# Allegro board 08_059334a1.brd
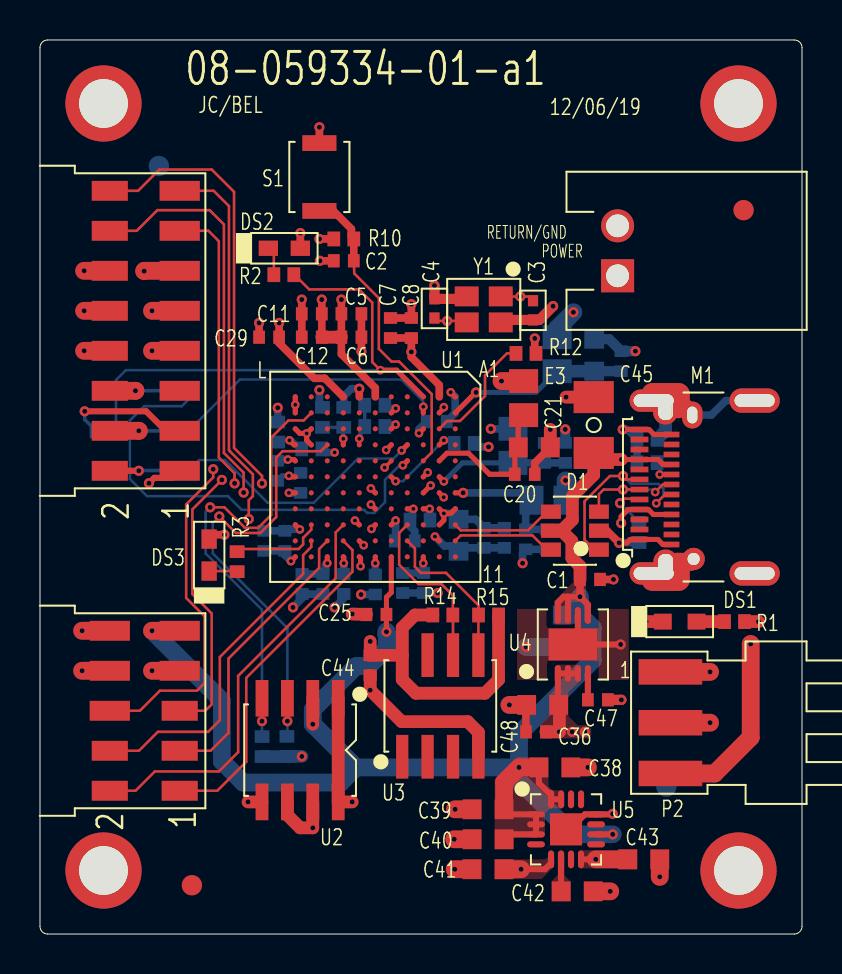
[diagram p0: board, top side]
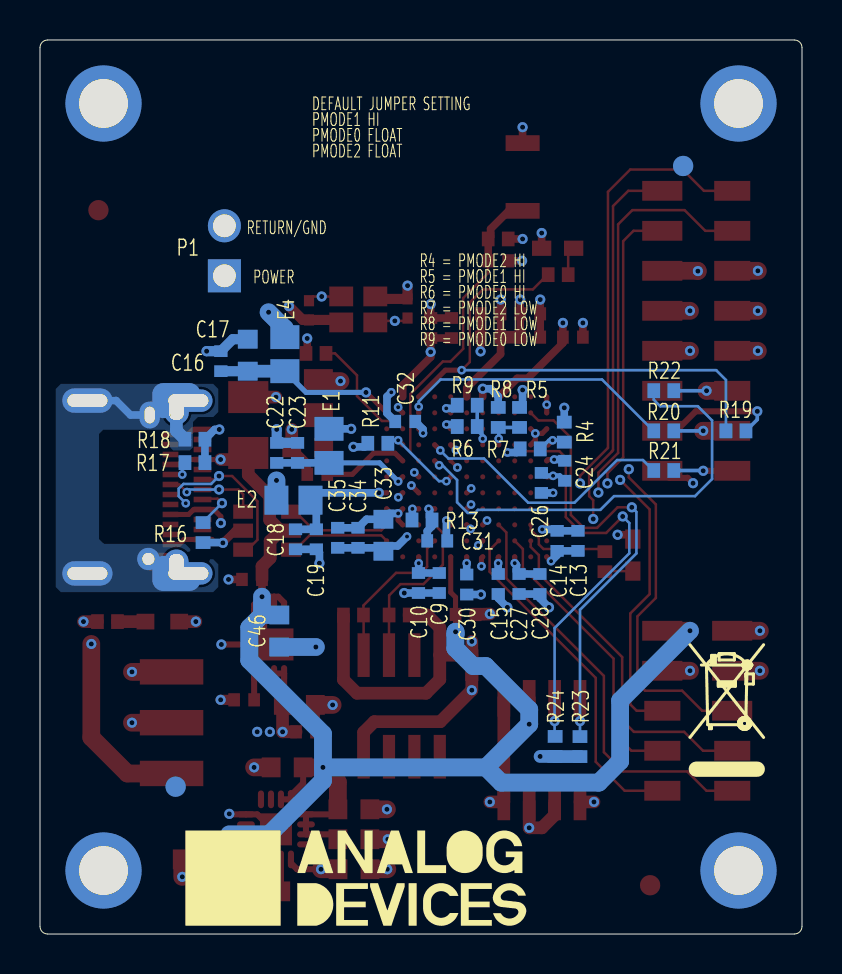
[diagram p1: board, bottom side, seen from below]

Outline 38.1 x 44.7 mm; copper layers: TOP, L2_GND, L3_SIG, L4_PWR, L5_GND, BOTTOM. Coordinates in mm from the lower left corner of the outline.
Outline path: 0,44.32 0,0.38 arc(0.11,0.11) 0.38,0 37.72,0 arc(37.99,0.11) 38.1,0.38 38.1,44.32 arc(37.99,44.59) 37.72,44.7 0.38,44.7 arc(0.11,44.59) 0,44.32

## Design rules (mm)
constraint set DEFAULT: min track width 0.127

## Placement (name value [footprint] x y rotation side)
C1  1uF  [C0402]  27.5 17.73 0 top
C2  0.1uF  [C0402]  15.19 33.66 180 top
C3  13PF  [C0402H22]  24.65 31.19 270 top
C4  13PF  [C0402H22]  19.72 31.28 90 top
C5  0.1uF  [C0402]  15.57 31.01 0 top
C6  0.1uF  [C0402]  15.57 29.84 0 top
C7  0.1uF  [C0402]  17.53 30.3 90 top
C8  0.01UF  [C0402]  18.57 30.3 90 top
C9  0.1uF  [C0402]  18.14 17.55 270 bottom
C10  0.01UF  [C0402]  19.18 17.55 270 bottom
C11  0.1uF  [C0402]  13.59 31.01 180 top
C12  0.1uF  [C0402]  13.59 29.84 180 top
C13  0.1uF  [C0402]  11.2 19.66 270 bottom
C14  0.1uF  [C0402]  12.24 19.66 270 bottom
C15  0.01UF  [C0402]  15.19 17.5 270 bottom
C16  0.1uF  [C0402]  29.06 28.64 90 bottom
C17  22uF  [C0603]  27.71 28.94 90 bottom
C18  2.2uF  [C0402]  25.32 19.74 270 bottom
C19  0.1uF  [C0402]  24.28 19.74 270 bottom
C20  0.1uF  [C0402]  24.24 22.99 0 top
C21  22uF  [C0603]  24.71 24.33 0 top
C22  0.01UF  [C0402]  26.26 24.06 90 bottom
C23  0.1uF  [C0402]  25.22 24.06 90 bottom
C24  0.1uF  [C0402]  11.86 23.16 270 bottom
C25  0.1uF  [C0402]  16.82 15.98 180 top
C26  0.1uF  [C0402]  13.03 22.56 90 bottom
C27  0.01UF  [C0402]  14.15 17.5 270 bottom
C28  0.1uF  [C0402]  13.11 17.5 270 bottom
C29  0.1uF  [C0402]  11.46 29.84 180 top
C30  0.1uF  [C0402]  16.76 17.48 270 bottom
C31  0.01UF  [C0402]  18.24 19.66 0 bottom
C32  0.01UF  [C0402]  19.84 25.63 0 bottom
C33  22uF  [C0603]  20.93 19.94 90 bottom
C34  0.1uF  [C0402]  22.2 19.81 90 bottom
C35  0.01UF  [C0402]  23.22 19.81 90 bottom
C36  1uF  [C0402]  24.8 10.11 180 top
C38  4.7uF  [C0603]  25.74 8.33 0 top
C39  4.7uF  [C0603]  22.41 6.24 180 top
C40  4.7uF  [C0603]  22.41 4.74 180 top
C41  4.7uF  [C0603]  22.4 3.24 180 top
C42  4.7uF  [C0603]  26.86 2.13 0 top
C43  4.7uF  [C0603]  30.19 3.73 0 top
C44  0.1uF  [C0402]  16.51 13.44 270 top
C45  10UF  [C1206H71]  27.69 25.45 90 top
C46  10uF  [C0603]  26.14 15.15 270 bottom
C47  1UF  [C0402]  27.89 11.71 0 top
C48  10uF  [C0603]  25.13 11.46 180 top
D1  82400102  [SOT23_6-2]  26.75 20.17 90 top
DS1  LTST-C191KGKT  [LED0603_A]  31.98 15.62 0 top
DS2  LTST-C191KSKT  [LED0603]  12.22 34.29 0 top
DS3  LTST-C191KSKT  [LED0603]  8.46 18.95 90 top
E1  600OHM AT 100MEGHZ  [L0805]  23.65 24.41 270 bottom
E2  600OHM AT 100MEGHZ  [L0805]  25.43 21.69 180 bottom
E3  600OHM AT 100MEGHZ  [L0805]  24.18 26.8 90 top
E4  600OHM AT 100MEGHZ  [L0805]  25.86 28.99 90 bottom
M1  DX07S024JJ3  [MDX07S024JJ3]  37.53 22.35 90 top
NOREF  -  []  13.9 20.16 0 top
NOREF#2  -  [unnamed#2]  30.68 18.03 270 top
NOREF#3  -  [unnamed#2]  34.92 41.53 0 top
NOREF#4  -  [unnamed#2]  30.68 26.67 270 top
NOREF#5  -  []  3.56 0 90 top
NOREF#6  -  []  0 1.44 0 top
NOREF#7  -  []  -234.21 -121.03 0 top
NOREF#8  -  []  -229.13 283.51 0 top
NOREF#9  -  [unnamed#2]  35.18 36.2 0 top
NOREF#10  -  [unnamed#2]  34.92 3.18 0 top
NOREF#11  -  [unnamed#2]  31.27 26.35 0 top
NOREF#12  -  [unnamed#2]  3.18 3.18 0 top
NOREF#13  -  []  3.18 41.53 0 top
NOREF#14  -  []  34.92 3.18 90 top
NOREF#15  -  []  37.99 44.59 0 top
NOREF#16  -  [unnamed#2]  7.59 2.44 0 top
NOREF#17  -  []  38.02 0.14 0 top
NOREF#18  -  []  0.08 44.55 0 top
NOREF#19  -  [unnamed#2]  3.18 41.53 0 top
NOREF#20  -  []  9.89 4.16 0 top
NOREF#21  -  [unnamed#2]  31.28 18.35 0 top
NOREF#22  -  []  37.53 28.36 0 top
NOREF#23  -  []  0.12 0.1 0 top
NOREF#24  -  []  3.96 7.92 180 bottom
NOREF#25  -  [unnamed#2]  5.94 38.4 180 bottom
NOREF#26  -  [unnamed#2]  31.32 7.37 180 bottom
NOREF#27  -  []  22.28 2.79 180 bottom
P1  S2B-XH-A(LF)(SN)  [CNTHMHDRRA1X2L291W452H240]  28.88 32.91 90 top
P2  TSM-103-01-L-SH  [CNSMMHDRRA1X3L300W100H125]  36.8 10.57 270 top
P3  10112690-G03-08ULF  [CNSMMHDRRA2X8L630W59H169]  0.74 30.16 90 top
P4  10112690-G03-05ULF  [CNSMMHDRRA2X5L394W59H169]  0.74 11.16 90 top
R1  330  [R0402]  34.73 15.62 180 top
R2  330  [R0402]  12.19 32.97 0 top
R3  330  [R0402]  9.86 18.62 90 top
R4  0  [R0402]  11.89 25.1 270 bottom
R5  0  [R0402]  14.12 25.83 270 bottom
R6  0  [R0402]  16.74 25.37 180 bottom
R7  0  [R0402]  13.59 24.26 0 bottom
R8  0  [R0402]  15.19 25.83 90 bottom
R9  0  [R0402]  16.74 26.44 0 bottom
R10  100K  [R0402]  15.19 34.75 0 top
R11  10K  [R0402]  21.21 24.54 180 bottom
R12  200  [R0402]  24.3 29.03 0 top
R13  6.04K  [R0402]  19 20.7 180 bottom
R14  2K  [R0402]  20.14 15.95 0 top
R15  2K  [R0402]  22.43 15.95 180 top
R16  5.1K  [R0402]  29.95 20.07 270 bottom
R17  5.1K  [R0402]  30.35 23.57 180 bottom
R18  0  [R0402]  30.35 24.74 180 bottom
R19  22  [R0402]  3.3 25.16 180 bottom
R20  22  [R0402]  6.91 25.16 0 bottom
R21  22  [R0402]  6.91 23.18 0 bottom
R22  22  [R0402]  6.91 27.17 0 bottom
R23  10K  [R0402]  11.1 9.37 270 bottom
R24  10K  [R0402]  12.34 9.38 270 bottom
S1  B3U-1000P  [SWSML118W98H69]  13.97 37.85 270 top
U1  CYUSB3014-BZXC  [BGA121_A]  16.76 22.86 180 top
U2  LTC1470CS8#PBF  [SO8NB-5]  13 9.19 180 top
U3  M24M02-DRMN6TP  [SO8]  20.02 11.4 0 top
U4  ADM7172ACPZ-3.3  [DFN8_3X3_PAD2_44X1_6_A]  26.64 14.48 0 top
U5  ADP322ACPZ-165  [QFN16_3X3_PAD1_6X1_6]  26.3 5.23 270 top
Y1  19.200MEGHZ  [YSML98W79H26]  22.19 31.23 180 top

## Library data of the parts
C1 C36 = CAP: User Part Number: UPN; Tolerance: 20; alternate symbols: (); part number: CAP_SM-1UF,16V,20,E020695,C0402; tolerance: 20
C2 C5-C7 C9 C11-C14 C16 C19 C20 C23-C26 C28-C30 C34 C44 = CAP: User Part Number: UPN; Tolerance: 10; alternate symbols: (); part number: CAP_SM-0.1UF,10V,10,E016510,C0402; tolerance: 10
C3 C4 = CAP: Tolerance: 5; User Part Number: UPN; alternate symbols: (); part number: CAP_SM-13PF,50V,5,E033176,C0402H22; tolerance: 5
C8 C10 C15 C22 C27 C31 C32 C35 = CAP: User Part Number: UPN; Tolerance: 10; alternate symbols: (); part number: CAP_SM-0.01UF,25V,10,E007203,C0402; tolerance: 10
C17 C21 C33 = CAP: User Part Number: UPN; Tolerance: 20; alternate symbols: (); part number: CAP_SM-22UF,4V,20,E017158,C0603; tolerance: 20
C18 = CAP: User Part Number: UPN; Tolerance: 10; alternate symbols: (); part number: CAP_SM-2.2UF,6.3V,10,E021628,C0402; tolerance: 10
C38-C43 = CAP: User Part Number: UPN; Tolerance: 10; alternate symbols: (); part number: CAP_SM-4.7UF,16V,10,E020112,C0603; tolerance: 10
C45 = CAP: Tolerance: 10; User Part Number: UPN; alternate symbols: (); part number: CAP_SM-10UF,50V,10,E026881,C1206H71; tolerance: 10
C46 C48 = CAP: User Part Number: UPN; Tolerance: 20; alternate symbols: (); part number: CAP_SM-10UF,16V,20,E020896,C0603; tolerance: 20
C47 = CAP: User Part Number: UPN; Tolerance: 20; alternate symbols: (); part number: CAP_SM-1UF,16V,20,E030046,C0402; tolerance: 20
D1 = DIOTVS6P: User Part Number: UPN; Tolerance: N/A; alternate symbols: (); part number: DIOTVS6P_SM-82400102,5V,N/A,E023105,SOT23_6-2; tolerance: N/A
DS1 = DIOLED: User Part Number: UPN; Tolerance: N/A; alternate symbols: (); part number: DIOLED_SM-LTST-C191KGKT,2V,N/A,E033001,LED0603_A; tolerance: N/A
DS2 DS3 = DIOLED: Tolerance: N/A; User Part Number: UPN; alternate symbols: (); part number: DIOLED_SM-LTST-C191KSKT,2V,N/A,E025936,LED0603; tolerance: N/A
E1-E4 = FERRITE: User Part Number: UPN; Tolerance: 25; alternate symbols: (); part number: FERRITE_SM-600OHM AT 100MEGHZ,25,E022193,L0805; tolerance: 25
M1 = MODUSB24P_6PSHLD: User Part Number: UPN; Tolerance: N/A; alternate symbols: (); part number: MODUSB24P_6PSHLD_SM-DX07S024JJ3,E025013,MDX07S024JJ3; tolerance: N/A
P1 = CN2P: User Part Number: UPN; Tolerance: N/A; alternate symbols: (); part number: CN2P_TH-S2B-XH-A(LF)(SN),E032336,CNTHMHDRRA1X2L291W452H240; tolerance: N/A
P2 = CN3P: User Part Number: UPN; Tolerance: N/A; alternate symbols: (); part number: CN3P_SM-TSM-103-01-L-SH,E038809,CNSMMHDRRA1X3L300W100H125; tolerance: N/A
P3 = CN16P_ODD_EVEN: User Part Number: UPN; Tolerance: N/A; alternate symbols: (CNSMMHDRRA2X8L630W59H169X); part number: CN16P_ODD_EVEN_SM-10112690-G03-08ULF,E038806,CNSMMHDRRA2X8L630W59H169; tolerance: N/A
P4 = CN10P_ODD_EVEN: User Part Number: UPN; Tolerance: N/A; alternate symbols: (CNSMMHDRRA2X5L394W59H169X); part number: CN10P_ODD_EVEN_SM-10112690-G03-05ULF,E038807,CNSMMHDRRA2X5L394W59H169; tolerance: N/A
R1-R3 = RES: User Part Number: UPN; Tolerance: 5; alternate symbols: (R0402L); part number: RES_SM-330,E003462,1/16W,5,R0402; tolerance: 5
R4-R9 R18 = RES: User Part Number: UPN; Tolerance: N/A; alternate symbols: (); part number: RES_SM-0,E030156,1/16W,N/A,R0402; tolerance: N/A
R10 = RES: User Part Number: UPN; Tolerance: 1; alternate symbols: (R0402L,R0402L_ALT); part number: RES_SM-100K,E003796,1/16W,1,R0402; tolerance: 1
R11 R23 R24 = RES: User Part Number: UPN; Tolerance: 1; alternate symbols: (R0402L,R0402L_ALT); part number: RES_SM-10K,E003751,1/10W,1,R0402; tolerance: 1
R12 = RES: User Part Number: UPN; Tolerance: 1; alternate symbols: (R0402L); part number: RES_SM-200,E003753,1/10W,1,R0402; tolerance: 1
R13 = RES: User Part Number: UPN; Tolerance: 1; alternate symbols: (R0402L); part number: RES_SM-6.04K,E004030,1/16W,1,R0402; tolerance: 1
R14 R15 = RES: User Part Number: UPN; Tolerance: 1; alternate symbols: (R0402L,R0402L_ALT); part number: RES_SM-2K,E003752,1/10W,1,R0402; tolerance: 1
R16 R17 = RES: User Part Number: UPN; Tolerance: 1; alternate symbols: (R0402L); part number: RES_SM-5.1K,E019615,1/16W,1,R0402; tolerance: 1
R19-R22 = RES: User Part Number: UPN; Tolerance: 5; alternate symbols: (); part number: RES_SM-22,E033672,1/10W,5,R0402; tolerance: 5
S1 = SWSPST2PIN_V2: Tolerance: N/A; User Part Number: UPN; alternate symbols: (); part number: SWSPST2PIN_V2_SM-B3U-1000P,E016303,SWSML118W98H69; tolerance: N/A
U1 = ICCYUSB301X: User Part Number: UPN; Tolerance: N/A; alternate symbols: (); part number: ICCYUSB301X_SM-CYUSB3014-BZXC,E022930,BGA121_A; tolerance: N/A
U2 = ADLTC1470: Tolerance: N/A; User Part Number: UPN; alternate symbols: (); part number: ADLTC1470_SM-LTC1470CS8#PBF,E039502,SO8NB-5; tolerance: N/A
U3 = ICM24M02: Tolerance: N/A; User Part Number: UPN; alternate symbols: (); part number: ICM24M02_SM-M24M02-DRMN6TP,E023121,SO8; tolerance: N/A
U4 = ADM7172: Tolerance: N/A; User Part Number: UPN; alternate symbols: (); part number: ADM7172_SM-ADM7172ACPZ-3.3,E022887,DFN8_3X3_PAD2_44X1_6_A; tolerance: N/A
U5 = ADP322: User Part Number: UPN; Tolerance: N/A; alternate symbols: (); part number: ADP322_SM-ADP322ACPZ-165,E038808,QFN16_3X3_PAD1_6X1_6; tolerance: N/A
Y1 = XTAL4PIN_V3: Tolerance: N/A; User Part Number: UPN; alternate symbols: (); part number: XTAL4PIN_V3_SM-19.200MEGHZ,E023118,YSML98W79H26; tolerance: N/A

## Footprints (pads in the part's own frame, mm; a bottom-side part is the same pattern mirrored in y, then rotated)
BGA121_A
  round 0.254 smd: A1(-4,-4) A2(-4,-3.2) A3(-4,-2.4) A4(-4,-1.6) A5(-4,-0.8) A6(-4,0) A7(-4,0.8) A8(-4,1.6) A9(-4,2.4) A10(-4,3.2) A11(-4,4) B1(-3.2,-4) B2(-3.2,-3.2) B3(-3.2,-2.4) B4(-3.2,-1.6) B5(-3.2,-0.8) B6(-3.2,0) B7(-3.2,0.8) B8(-3.2,1.6) B9(-3.2,2.4) B10(-3.2,3.2) B11(-3.2,4) C1(-2.4,-4) C2(-2.4,-3.2) C3(-2.4,-2.4) C4(-2.4,-1.6) C5(-2.4,-0.8) C6(-2.4,0) C7(-2.4,0.8) C8(-2.4,1.6) C9(-2.4,2.4) C10(-2.4,3.2) C11(-2.4,4) D1(-1.6,-4) D2(-1.6,-3.2) D3(-1.6,-2.4) D4(-1.6,-1.6) D5(-1.6,-0.8) D6(-1.6,0) D7(-1.6,0.8) D8(-1.6,1.6) D9(-1.6,2.4) D10(-1.6,3.2) D11(-1.6,4) E1(-0.8,-4) E2(-0.8,-3.2) E3(-0.8,-2.4) E4(-0.8,-1.6) E5(-0.8,-0.8) E6(-0.8,0) E7(-0.8,0.8) E8(-0.8,1.6) E9(-0.8,2.4) E10(-0.8,3.2) E11(-0.8,4) F1(0,-4) F2(0,-3.2) F3(0,-2.4) F4(0,-1.6) F5(0,-0.8) F6(0,0) F7(0,0.8) F8(0,1.6) F9(0,2.4) F10(0,3.2) F11(0,4) G1(0.8,-4) G2(0.8,-3.2) G3(0.8,-2.4) G4(0.8,-1.6) G5(0.8,-0.8) G6(0.8,0) G7(0.8,0.8) G8(0.8,1.6) G9(0.8,2.4) G10(0.8,3.2) G11(0.8,4) H1(1.6,-4) H2(1.6,-3.2) H3(1.6,-2.4) H4(1.6,-1.6) H5(1.6,-0.8) H6(1.6,0) H7(1.6,0.8) H8(1.6,1.6) H9(1.6,2.4) H10(1.6,3.2) H11(1.6,4) J1(2.4,-4) J2(2.4,-3.2) J3(2.4,-2.4) J4(2.4,-1.6) J5(2.4,-0.8) J6(2.4,0) J7(2.4,0.8) J8(2.4,1.6) J9(2.4,2.4) J10(2.4,3.2) J11(2.4,4) K1(3.2,-4) K2(3.2,-3.2) K3(3.2,-2.4) K4(3.2,-1.6) K5(3.2,-0.8) K6(3.2,0) K7(3.2,0.8) K8(3.2,1.6) K9(3.2,2.4) K10(3.2,3.2) K11(3.2,4) L1(4,-4) L2(4,-3.2) L3(4,-2.4) L4(4,-1.6) L5(4,-0.8) L6(4,0) L7(4,0.8) L8(4,1.6) L9(4,2.4) L10(4,3.2) L11(4,4)
C0402
  rect 0.584x0.66 smd: 1(-0.5,0) 2(0.5,0)
C0402H22
  rect 0.559x0.508 smd: 1(-0.48,0) 2(0.48,0)
C0603
  rect 0.94x0.991 smd: 1(-0.8,0) 2(0.8,0)
C1206H71
  rect 1.6x2.007 smd: 1(-1.397,0) 2(1.397,0)
CNSMMHDRRA1X3L300W100H125
  rect 1.27x3.175 smd: 1(-2.54,-5.283) 2(0,-5.283) 3(2.54,-5.283)
CNSMMHDRRA2X5L394W59H169
  rect 0.991x1.803 smd: 1(-4,-6.248) 2(-4,-2.753) 3(-2,-6.248) 4(-2,-2.753) 5(0,-6.248)
  rect 0.991x2.007 smd: 6(0,-2.753) 7(2,-6.248) 8(2,-2.753) 9(4,-6.248) 10(4,-2.753)
CNSMMHDRRA2X8L630W59H169
  rect 0.991x2.007 smd: 1(-7,-6.248) 3(-5,-6.248) 5(-3,-6.248) 7(-1,-6.248) 9(1,-6.248) 11(3,-6.248) 13(5,-6.248) 15(7,-6.248)
  rect 0.991x1.803 smd: 2(-7,-2.753) 4(-5,-2.753) 6(-3,-2.753) 8(-1,-2.753) 10(1,-2.753) 12(3,-2.753) 14(5,-2.753) 16(7,-2.753)
CNTHMHDRRA1X2L291W452H240
  rect 1.651x1.651 hole 1.143: 1(0,0)
  round 1.651 hole 1.143: 2(2.499,0)
DFN8_3X3_PAD2_44X1_6_A
  oval 0.305x0.838 smd: 1(-0.749,-1.45) 2(-0.249,-1.45) 3(0.249,-1.45) 4(0.749,-1.45) 5(0.749,1.45) 6(0.249,1.45) 7(-0.249,1.45) 8(-0.749,1.45)
  rect 2.438x1.6 smd: PAD(0,0)
L0805
  rect 1.194x1.448 smd: 1(-0.851,0) 2(0.851,0)
LED0603
  rect 0.965x0.762 smd: A(0.8,0) C(-0.8,0)
LED0603_A
  rect 0.889x0.787 smd: A(0.843,0) C(-0.843,0)
MDX07S024JJ3
  oval 1.219x2.515 hole 0.635x2.007 unplated: (-4.32,1.801) (4.32,1.801)
  oval 1.346x1.016 hole 0.838x0.508 unplated: (3.599,4.915)
  rect 0.279x0.889 smd: A1(-2.624,7.556) A2(-2.126,7.556) A3(-1.626,7.556) A4(-1.125,7.556) A5(-0.625,7.556) A6(-0.125,7.556) A7(0.376,7.556) A8(0.874,7.556) A9(1.374,7.556) A10(1.874,7.556) A11(2.375,7.556) A12(2.875,7.556)
  rect 0.279x0.787 smd: B1(2.624,5.956) B2(2.126,5.956) B3(1.626,5.956) B4(1.125,5.956) B5(0.625,5.956) B6(0.125,5.956) B7(-0.376,5.956) B8(-0.874,5.956) B9(-1.374,5.956) B10(-1.874,5.956) B11(-2.375,5.956) B12(-2.875,5.956)
  custom 0.438x0.438 hole 0.002: SH4(4.32,6.251) SH5(-4.32,6.251)
  round 1.118 hole 0.61: SH6(-3.599,4.849)
QFN16_3X3_PAD1_6X1_6
  oval 0.305x0.889 smd: 1(-0.749,-1.501) 2(-0.249,-1.501) 3(0.249,-1.501) 4(0.749,-1.501) 9(0.749,1.501) 10(0.249,1.501) 11(-0.249,1.501) 12(-0.749,1.501)
  oval 0.889x0.305 smd: 5(1.501,-0.749) 6(1.501,-0.249) 7(1.501,0.249) 8(1.501,0.749) 13(-1.501,0.749) 14(-1.501,0.249) 15(-1.501,-0.249) 16(-1.501,-0.749)
  rect 1.6x1.6 smd: PAD(0,0)
R0402
  rect 0.635x0.737 smd: 1(-0.5,0) 2(0.5,0)
SO8
  rect 0.61x2.184 smd: 1(-1.905,-2.54) 2(-0.635,-2.54) 3(0.635,-2.54) 4(1.905,-2.54) 5(1.905,2.54) 6(0.635,2.54) 7(-0.635,2.54) 8(-1.905,2.54)
SO8NB-5
  rect 0.635x1.829 smd: 1(-1.905,-2.591) 2(-0.635,-2.591) 3(0.635,-2.591) 4(1.905,-2.591) 5(1.905,2.591) 6(0.635,2.591) 7(-0.635,2.591) 8(-1.905,2.591)
SOT23_6-2
  rect 0.711x0.991 smd: 1(-0.95,-1.199) 2(0,-1.199) 3(0.95,-1.199) 4(0.95,1.199) 5(0,1.199) 6(-0.95,1.199)
SWSML118W98H69
  rect 0.787x1.702 smd: 1(-1.694,0) 2(1.694,0)
unnamed#2
  oval 1.118x2.413 hole 0.635x2.007 unplated: (0,0)
YSML98W79H26
  rect 1.194x0.991 smd: 1(-0.851,-0.65) 2(0.851,-0.65) 3(0.851,0.65) 4(-0.851,0.65)

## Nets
AVDD: C18.1 C19.1 E2.2(N2) U1.A7
DGND: C1.2(N2) C2.2(N2) C3.2(N2) C4.2(N2) C5.2(N2) C6.2(N2) C7.2(N2) C8.2(N2) C9.2(N2) C10.2(N2) C11.2(N2) C12.2(N2) C13.2(N2) C14.2(N2) C15.2(N2) C16.2(N2) C17.2(N2) C18.2(N2) C19.2(N2) C20.2(N2) C21.2(N2) C22.2(N2) C23.2(N2) C24.2(N2) C25.2(N2) C26.2(N2) C27.2(N2) C28.2(N2) C29.2(N2) C30.2(N2) C31.2(N2) C32.2(N2) C33.2(N2) C34.2(N2) C35.2(N2) C36.2(N2) C38.2(N2) C39.2(N2) C40.2(N2) C41.2(N2) C42.2(N2) C43.2(N2) C44.2(N2) C45.2(N2) C46.2(N2) C47.2(N2) C48.2(N2) D1.2 DS1.C M1.A1 M1.A12 M1.B1 M1.B12 P1.2(N2) P3.7 P3.8 P3.9 P4.7 P4.8 R7.2(N2) R8.2(N2) R9.2(N2) R11.1 R12.2(N2) R13.2(N2) R16.2(N2) R17.2(N2) R18.2(N2) S1.1 U1.A1 U1.A8 U1.B7 U1.B8 U1.B9 U1.D8 U1.E2 U1.G1 U1.G11 U1.K3 U1.K4 U1.L1 U1.L2 U1.L3 U1.L6 U1.L11 U2.5 U3.4 U4.6 U4.PAD U5.12 U5.PAD Y1.2 Y1.4
DUT_3P3V: C36.1 C48.1 U2.6 U2.7 U4.1 U4.2(VOUT2) U4.3
DUT_EXT: P1.1 P2.3(N3)
DUT_REG_PWR: P2.1 U2.1 U2.8(OUT_2)
DUT_SUPPLY: P2.2 P3.10 P3.11 P3.12
FX3_1P2V: C24.1 C26.1 C27.1 C28.1 C29.1 C30.1 C31.1 C32.1 C33.1 C34.1 C35.1 C43.1 E2.1 E3.2(N2) E4.2(N2) U1.B10 U1.C3 U1.E9 U1.F11 U1.H1 U1.J11 U1.L5 U1.L7 U5.8(VOUT3)
FX3_1P8V: C42.1 U5.6
FX3_3P3V: C5.1 C6.1 C7.1 C8.1 C9.1 C10.1 C11.1 C12.1 C13.1 C14.1 C15.1 C41.1 C44.1 DS2.A(P) DS3.A(P) E1.1 P4.10(N5) R1.1 R4.1 R5.1 R6.1 R10.1 R14.1 R15.1 R23.2(N2) R24.2(N2) U1.B1 U1.C11 U1.E3 U1.F1 U1.H11 U1.L9 U3.8 U5.5
FX3_CTL0: U1.K8
FX3_CTL1: U1.K7
FX3_CTL2: U1.J7
FX3_CTL3: U1.H7
FX3_CTL4: U1.G7
FX3_CTL5: U1.G6
FX3_CTL6: U1.K6
FX3_CTL7: U1.H8
FX3_CTL8: U1.G5
FX3_CTL9: U1.H6
FX3_CTL10: U1.K5
FX3_CTL11: U1.J5
FX3_CTL12: U1.H5
FX3_DQ0: P3.1 U1.F9
FX3_DQ1: P3.16(N8) U1.F7
FX3_DQ2: P3.15 U1.G10
FX3_DQ3: P3.14 U1.G9
FX3_DQ4: P3.13 U1.F8
FX3_DQ5: P4.1 U1.H10
FX3_DQ6: P4.2 U1.H9
FX3_DQ7: P4.3 U1.J10
FX3_DQ8: U1.J9
FX3_DQ9: U1.K11
FX3_DQ10: U1.F10
FX3_DQ11: U1.L10
FX3_DQ12: P4.4 U1.K10
FX3_DQ13: R3.2(N2) U1.K9
FX3_DQ14: U1.J8
FX3_DQ15: U1.G8
FX3_DQ16: R23.1 U1.K2 U2.4
FX3_DQ17: R24.1 U1.J4 U2.3
FX3_DQ18: U1.K1
FX3_DQ19: U1.J2
FX3_DQ20: U1.J3
FX3_DQ21: U1.J1
FX3_DQ22: U1.H2
FX3_DQ23: U1.H3
FX3_DQ24: U1.F4
FX3_DQ25: U1.G2
FX3_DQ26: U1.G3
FX3_DQ27: U1.F3
FX3_DQ28: U1.F5
FX3_DQ29: U1.E1
FX3_DQ30: P4.5 U1.E5
FX3_DQ31: P4.6 U1.E4
FX3_GPIO_52: U1.D3
FX3_GPIO_57: U1.C4
FX3_PCLK: U1.J6
FX3_PMODE_0: R6.2(N2) R9.1 U1.G4
FX3_PMODE_1: R5.2(N2) R8.1 U1.H4
FX3_PMODE_2: R4.2(N2) R7.1 U1.L4
FX3_SCL: R14.2(N2) U1.D9 U3.6
FX3_SDA: R15.2(N2) U1.D10 U3.5
FX3_STATUS: U1.F2
FX3_VBUS: C1.1 C25.1 C38.1 C39.1 C40.1 C45.1 C46.1 D1.5(VDD) M1.A4 M1.A9 M1.B4(VBUS_4) M1.B9 P4.9 U1.E11 U2.2 U4.5 U4.7 U4.8 U5.1 U5.2 U5.3 U5.10 U5.15 U5.16
SPI_CSB: R2.2(N2) R19.1 U1.C1
SPI_CSB2: U1.D1
SPI_CSB3: U1.D2
SPI_MISO: R20.2(N2) U1.C2
SPI_MOSI: R22.2(N2) U1.D5
SPI_SCLK: R21.2(N2) U1.D4
SS_DM: D1.6 U1.A10
SS_DP: D1.4 U1.A9
SSDM: D1.1 M1.A7 M1.B7
SSDP: D1.3 M1.A6 M1.B6
U3RX_VDDQ: C16.1 C17.1 E4.1 U1.A2
U3TX_VDDQ: C20.1 C21.1 E3.1 U1.B5
UNNAMED_4_ADM7172_I197_SS: C47.1 U4.4
UNNAMED_4_CAP_I116_N1: C2.1 R10.2(N2) S1.2(B) U1.C5
UNNAMED_4_CAP_I140_N1: C22.1 C23.1 E1.2(N2) U1.B6
UNNAMED_4_CN16PODDEVEN_I209_N2: P3.3 R19.2(N2)
UNNAMED_4_CN16PODDEVEN_I210_N1: P3.2 R21.1
UNNAMED_4_CN16PODDEVEN_I210_N2: P3.4 R20.1
UNNAMED_4_CN16PODDEVEN_I210_N3: P3.6 R22.1
UNNAMED_4_DIOLED_I220_N: DS3.C R3.1
UNNAMED_4_DIOLED_I221_N: DS2.C R2.1
UNNAMED_4_DIOLED_I222_P: DS1.A(P) R1.2(N2)
UNNAMED_4_ICCYUSB301X_I101_FSLC: R11.2(N2) U1.B2 U1.B4 U1.E6
UNNAMED_4_ICCYUSB301X_I101_RU_1: R12.1 U1.B3
UNNAMED_4_ICCYUSB301X_I101_RUSB: R13.1 U1.C8
UNNAMED_4_MODUSB24P6PSHLD_I16_1: M1.B5 R17.1
UNNAMED_4_MODUSB24P6PSHLD_I16_2: M1.SH4 M1.SH5 M1.SH6 R18.1
UNNAMED_4_MODUSB24P6PSHLD_I165_: M1.A5 R16.1
XTALIN: C4.1 U1.C6 Y1.3(N2)
XTALOUT: C3.1 U1.C7(XTALOUT) Y1.1

Pads without a net: M1 A2 A3 A8 A10 A11 B2 B3 B8 B10 B11; P3 5; U1 A3 A4 A5 A6 A11 B11 C9 C10 D6 D7 D11 E7 E8 E10 F6 L8; U3 1 2 3 7; U5 4 7 9 11 13 14

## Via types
v1: diameter 0.508, hole 0.254, TOP to BOTTOM, 103 vias
v2: diameter 0.432, hole 0.203, TOP to BOTTOM, 46 vias

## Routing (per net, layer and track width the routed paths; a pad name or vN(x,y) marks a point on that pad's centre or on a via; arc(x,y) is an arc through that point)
AVDD: length 6.6
  TOP w0.254: U1.A7 v1(21.16,22.06)
  BOTTOM w0.381: v1(21.16,22.06) 24.21,22.06 E2.2 24.28,21.4 C19.1 C18.1
DGND: length 101.3
  TOP w0.254: v2(20.19,21.03) 20.19,20.69 U1.B9 ; v2(20.19,21.03) 20.54,21.03 U1.A8 ; v2(20.19,21.03) U1.B8 ; M1.B1 30.7,24.98 30.45,25.23 M1.A12 v1(29.13,25.23) ; U1.L6 12.55,22.86 12.5,22.91 v2(12.45,22.91) ; v2(16.03,18.39) 16.03,18.8 U1.G11 ; U1.L11 v2(12.55,18.64) ; v2(13.34,25.03) 13.34,24.69 U1.K4 ; v2(13.34,25.03) U1.K3 ; v2(13.34,25.03) 12.99,25.03 U1.L3 ; v1(28.96,19.56) 29.34,19.56 29.51,19.73 M1.A1 30.89,19.73 31.15,19.48 M1.B12 ; U1.L1 v2(12.76,26.47) U1.L2 ; U1.E2 v2(17.79,26.28) ; U1.A1 v2(20.54,27.09) ; v2(20.19,21.84) U1.B7 ; U1.D8 v2(18.67,21.26)
  TOP w0.305: U5.PAD 26.49,5.23 27.24,5.98 U5.12 28.61,5.98 v1(28.64,6.01) ; U4.6 26.89,14.73 U4.PAD v1(29.03,14.48)
  TOP w0.381: C36.2 24.3,11.42 C48.2 ; v1(28.96,19.56) 28.35,20.17 D1.2 ; C2.2 v1(14,33.66) ; C12.2 C11.2 v1(13.09,31.72) ; C5.2 C6.2 v1(16.07,29.13) ; v1(24.74,29.78) 24.74,29.09 R12.2 ; S1.1 v1(13.97,40.34) ; C7.2 C8.2 v1(18.57,31.5) ; v1(15.96,27.27) U1.G1 ; C1.2 v1(28.67,17.73) ; C21.2 24.74,23.56 C20.2 ; C29.2 v1(10.95,30.56)
  TOP w0.508: v1(19.72,32.42) C4.2 21.21,31.76 Y1.2 ; Y1.4 23.16,30.71 C3.2 24.97,30.71 v1(25.65,31.39) ; C47.2 v1(29.07,11.71)
  TOP w0.635: C44.2 v1(16.51,12.19) 18.08,10.62 21.39,10.62 21.92,10.08 U3.4 ; U2.5 v1(10.4,6.6) ; C45.2 v1(26.3,26.85) ; C21.2 v1(25.51,25.23) ; DS1.C v1(30.31,15.62) ; C25.2 v1(15.61,16)
  TOP w0.889: v1(23.47,11.46) C48.2 ; P3.8 v1(2.21,29.16) ; v1(5.6,13.16) P4.7 ; P3.7 v1(5.6,29.16) ; C41.2 v1(20.74,3.24) ; P4.8 v1(2.11,13.16) ; C40.2 v1(20.71,4.74) ; C42.2 v1(28.51,2.13) ; C39.2 v1(20.75,6.24) ; C43.2 v1(30.99,2.86) ; P3.9 v1(5.6,31.16) ; C38.2 v1(27.39,8.33)
  L2_GND w0.381: 28.88,34.41 P1.2 ; P1.2 28.88,36.42 ; P1.2 27.88,35.41 ; P1.2 29.88,35.41
  L5_GND w0.381: P1.2 29.88,35.41 ; P1.2 28.88,36.42 ; P1.2 27.88,35.41 ; P1.2 28.88,34.41
  BOTTOM w0.254: C24.2 12.11,22.91 v2(12.45,22.91) 12.89,22.91 C26.2
  BOTTOM w0.381: C9.2 C10.2 v1(19.89,17.05) ; C35.2 C34.2 21.77,20.74 C33.2 20.64,21.03 v2(20.19,21.03) ; v2(20.54,27.09) 20.75,26.87 20.75,26.04 C32.2 ; R17.2 R18.2 29.36,25.23 v1(29.13,25.23) ; v1(24.13,18.54) 24.13,19.08 C19.2 C18.2 ; v1(22.43,24.36) 21.89,24.36 R11.1 ; R7.2 14.27,24.08 v2(14.73,24.08) ; v1(28.96,19.56) 28.97,19.57 R16.2 ; v1(15.96,27.27) 15.57,27.27 15.19,26.89 R8.2 ; C15.2 15.19,16.79 v1(14.73,16.33) ; v2(12.55,18.64) 12.24,18.95 C14.2 C13.2 ; R9.2 17.4,26.28 v2(17.79,26.28) ; v1(12.65,16.33) 13.11,16.79 C28.2 C27.2 ; C30.2 v1(16.05,16.97) ; C31.2 18.74,20.15 18.5,20.39 R13.2 18.62,20.82 18.62,21.21 v2(18.67,21.26)
  BOTTOM w0.508: v1(29.77,29.14) C16.2 28.46,29.74 C17.2 ; v1(26.26,25.23) C22.2 C23.2
  BOTTOM w0.889: 26.14,14.35 v1(24.31,14.35)
DUT_3P3V: length 25.2
  TOP w0.305: U4.3 U4.2 U4.1 25.9,11.49 C48.1
  TOP w0.635: C48.1 25.97,11.42 v1(25.97,10.11) C36.1 ; U2.7 v1(13.64,5.31) 13,5.31 12.37,5.94 U2.6
  L3_SIG w0.889: v1(27.24,10.11) v1(26.61,10.11) v1(25.97,10.11) 15.93,10.11 13.64,7.82 v1(13.64,5.31)
DUT_EXT: length 36.3
  TOP w0.889: v1(35.53,14.5) 35.53,9.83 33.73,8.03 P2.3
  L4_PWR w0.889: v1(35.53,14.5) 33.38,16.66 28.52,16.66 25.45,19.74 25.45,23.03 28.88,26.45 P1.1
DUT_REG_PWR: length 32.5
  TOP w0.635: v1(15.61,6.6) U2.8 U2.1
  TOP w0.889: P2.1 v1(33.5,13.11)
  L4_PWR w0.889: v1(33.5,13.11) 35.03,11.58 35.03,9.86 32.36,7.19 16.19,7.19 v1(15.61,6.6)
DUT_SUPPLY: length 56.5
  TOP w0.889: P3.12 v1(2.21,33.16) ; P3.11 5.22,33.16 v1(5.21,33.15) ; P3.10 v1(2.21,31.16) ; v1(33.5,10.57) P2.2
  L3_SIG w0.889: 3.51,31.45 3.22,31.16 v1(2.21,31.16) ; 3.51,31.45 3.51,22.53 12.78,13.26 30.81,13.26 v1(33.5,10.57) ; 3.51,31.45 4.28,32.22 ; v1(5.21,33.15) 4.28,32.22 ; 4.28,32.22 3.34,33.16 v1(2.21,33.16)
FX3_1P2V: length 22.6
  TOP w0.254: U1.F11 v2(16.76,18.54) ; U1.C3 v2(18.95,25.04) ; U1.B10 v2(19.75,19.88) ; U1.E9 v2(17.78,20.68) ; U1.L5 12.7,23.72 v2(12.4,23.72) ; U1.L7 v2(12.45,22.06) ; U1.J11 v2(14.36,18.54)
  TOP w0.305: U5.8 27.79,3.73 v1(27.79,3.73)
  TOP w0.381: v1(11.96,30.56) C29.1 11.96,29.55 13.72,27.79 14.24,27.79 U1.H1
  TOP w0.889: v1(27.79,3.73) C43.1 ; E3.2 v1(23.08,27.65)
  BOTTOM w0.381: v2(18.95,25.04) 18.95,25.24 C32.1 ; C28.1 C27.1 14.27,18.13 14.27,18.45 v2(14.36,18.54) ; C24.1 11.92,23.72 v2(12.4,23.72) ; C31.1 17.78,19.7 v2(17.78,20.68) ; C26.1 12.45,22.05 v2(12.45,22.06) ; C35.1 C34.1 21.1,19.31 C33.1 20.66,19.41 20.22,19.41 v2(19.75,19.88) ; v2(16.76,18.54) C30.1
  BOTTOM w0.889: E2.1 v1(26.28,22.68) ; v1(26.67,31.09) 25.86,30.28 E4.2
FX3_1P8V: length 1.6
  TOP w0.305: U5.6 26.05,2.14 C42.1
FX3_3P3V: length 45.9
  TOP w0.254: U1.E3 v2(17.78,25.48) ; U1.C11 v2(19.16,18.54) ; v2(15.19,18.54) 15.19,18.83 U1.H11 ; U1.L9 v2(12.99,20.23)
  TOP w0.305: v1(24.05,3.24) 25.25,3.24 25.55,3.54 U5.5
  TOP w0.381: U1.F1 16.76,27.3 15.07,29 C6.1 C5.1 v1(15.07,31.72) ; v1(9.22,19.96) 8.67,19.96 DS3.A ; v1(13.97,34.75) R10.1 ; C12.1 C11.1 v1(14.09,31.72) ; C7.1 C8.1 v1(18.57,29.11) 18.57,28.84 19.96,27.45 U1.B1 ; DS2.A v1(13.02,35.05)
  TOP w0.635: R15.1 22.93,12.72 22.25,12.04 18.8,12.04 18.11,12.73 U3.8 ; U3.8 18.11,15.32 18.75,15.95 R14.1 ; U3.8 18.1,13.94 C44.1 v1(16.51,14.63) ; C12.1 C6.1 ; R1.1 v1(35.93,15.62)
  TOP w0.889: C41.1 v1(24.05,3.24) ; P4.10 v1(2.11,15.16)
  BOTTOM w0.381: v2(17.78,25.48) 17.34,25.48 R6.1 ; v2(12.99,20.23) 12.31,20.23 C14.1 C13.1 ; R4.1 v1(11.89,26.31) ; v2(15.19,18.54) C15.1 ; R5.1 13.97,26.48 v1(13.97,27.2) ; E1.1 v1(22.54,25.26) ; C9.1 C10.1 19.16,18.06 v2(19.16,18.54)
  BOTTOM w0.635: v1(13.09,8.88) R24.2 12.34,8.87 R23.2
FX3_DQ0: length 14.1
  TOP w0.254: U1.F9 16.57,20.27 v2(16.57,20.26)
  TOP w0.305: P3.1 6.63,22.81 5.71,22.81 v1(5.45,22.54)
  L3_SIG w0.127: v2(16.57,20.26) 15.48,20.26 15.32,20.42 13.79,20.42 13.32,20.89 11.29,20.89 10.57,21.62 10.01,21.62 9.4,22.23 5.77,22.23 v1(5.45,22.54)
FX3_DQ1: length 28.8
  TOP w0.127: P3.16 4.9,37.16 5.97,38.23 8.59,38.23 9.7,37.11 9.7,24.31 11.1,22.91 v1(11.1,22.53)
  TOP w0.254: U1.F7 v2(16.54,22.28)
  L3_SIG w0.127: v1(11.1,22.53) 11.1,22.23 11.67,21.65 15.92,21.65 v2(16.54,22.28)
FX3_DQ2: length 25.6
  TOP w0.127: P3.15 8.68,37.16 9.45,36.4 9.45,24.2 9.5,24.15 9.5,24.13 10.64,22.99 10.64,21.89 10.44,21.69 v1(10.44,20.75)
  TOP w0.254: U1.G10 v2(16.18,19.44)
  L3_SIG w0.127: v2(16.18,19.44) 15.94,19.44 15.21,20.17 13.68,20.17 13.21,20.64 10.91,20.64 10.79,20.75 v1(10.44,20.75)
FX3_DQ3: length 26.7
  TOP w0.127: v1(10.18,22.08) 10.18,23.07 9.19,24.06 9.19,35.48 8.48,36.2 5.87,36.2 4.83,35.16 P3.14
  TOP w0.254: v2(15.75,20.68) U1.G9
  L3_SIG w0.127: v2(15.75,20.68) 13.89,20.68 13.42,21.15 11.41,21.15 10.49,22.08 v1(10.18,22.08)
FX3_DQ4: length 22.2
  TOP w0.127: v1(9.73,22.53) 9.73,23.04 8.94,23.83 8.94,34.65 8.42,35.16 P3.13
  TOP w0.254: U1.F8 v2(16.55,21.48)
  L3_SIG w0.127: v1(9.73,22.53) 10.41,22.53 11.54,21.4 16.04,21.4 16.12,21.48 v2(16.55,21.48)
FX3_DQ5: length 17.4
  TOP w0.127: P4.1 8.87,7.16 10.31,8.61 10.31,12.81 15.62,18.12 15.62,19.2 U1.H10
FX3_DQ6: length 20.8
  TOP w0.127: U1.H9 14.78,20.08 14.78,17.78 9.91,12.91 9.91,9.09 8.94,8.13 5.74,8.13 4.78,7.16 P4.2
FX3_DQ7: length 14.5
  TOP w0.127: U1.J10 13.96,19.25 13.96,18.31 9.42,13.77 9.42,10.06 8.53,9.16 P4.3
FX3_DQ12: length 17
  TOP w0.127: U1.K10 13.56,19.35 13.16,18.95 13.16,18.01 8.99,13.85 8.99,10.69 8.41,10.11 5.89,10.11 4.95,9.16 P4.4
FX3_DQ13: length 4.6
  TOP w0.127: U1.K9 13.56,20.22 13.16,19.81 13.16,19.48 12.93,19.25 9.99,19.25 R3.2
FX3_DQ16: length 24
  TOP w0.127: v1(8.51,21.34) 9.22,21.34 10.25,20.31 10.91,20.31 11.56,20.95 11.56,24.82 12.42,25.68 13.18,25.68 U1.K2 ; U2.4 v1(11.1,10.64)
  BOTTOM w0.127: v1(8.51,21.34) 8.28,21.11 8.28,19.03 11.1,16.21 v1(11.1,10.64) 11.1,9.88 R23.1
FX3_DQ17: length 23.1
  TOP w0.127: U2.3 v1(12.37,10.64) ; v1(8.97,20.88) 9.79,20.05 11.02,20.05 11.81,20.85 11.81,23.82 12.13,24.14 14.05,24.14 U1.J4
  BOTTOM w0.127: v1(8.97,20.88) 8.64,20.55 8.64,19.03 12.37,15.3 v1(12.37,10.64) 12.37,9.91 R24.1
FX3_DQ30: length 23.3
  TOP w0.127: v1(9.09,22.71) 7.62,21.23 7.62,16.99 8.59,16.03 8.59,11.48 8.27,11.16 P4.5
  TOP w0.178: U1.E5 v2(17.23,23.33)
  L3_SIG w0.127: v2(17.23,23.33) 14.94,23.33 14.57,22.96 13.41,22.96 12.92,22.47 12.18,22.47 11.66,22.99 9.37,22.99 v1(9.09,22.71)
FX3_DQ31: length 26.4
  TOP w0.127: v1(8.66,23.24) 8.66,22.83 7.31,21.48 7.31,16.8 8.23,15.88 8.23,12.55 7.85,12.17 5.99,12.17 4.99,11.16 P4.6
  TOP w0.254: U1.E4 v2(17.3,24.2)
  L3_SIG w0.127: v1(8.66,23.24) 9.12,23.24 9.19,23.32 14.56,23.32 15.44,24.2 v2(17.3,24.2)
FX3_PMODE_0: length 2.1
  TOP w0.178: U1.G4 v2(15.96,24.77)
  BOTTOM w0.178: v2(15.96,24.77) 15.96,24.93 16.24,25.2 R6.2 R9.1
FX3_PMODE_1: length 1.9
  TOP w0.254: U1.H4 v2(15.16,24.77)
  BOTTOM w0.178: R5.2 R8.1 15.16,25.31 v2(15.16,24.77)
FX3_PMODE_2: length 1.8
  TOP w0.254: v2(12.47,24.69) 12.7,24.46 U1.L4
  BOTTOM w0.178: R4.2 11.98,24.69 v2(12.47,24.69) 12.66,24.69 R7.1
FX3_SCL: length 8.5
  TOP w0.127: U1.D9 17.96,20.05 17.96,18.47 18.93,17.5 20.07,17.5 20.64,16.93 R14.2 20.65,15.94 U3.6
FX3_SDA: length 7.9
  TOP w0.127: U1.D10 18.75,19.28 18.75,18.36 19.05,18.06 20.3,18.06 21.93,16.43 R15.2 21.92,15.94 U3.5
FX3_VBUS: length 92.4
  TOP w0.254: M1.B4 31.16,23.48 30.91,23.73 M1.A9 v1(29.07,23.73) ; v1(29.06,20.55) 29.06,20.88 29.41,21.23 M1.A4 30.42,21.23 30.67,20.98 M1.B9 ; U1.E11 17.56,17.08 17.32,16.84 C25.1 v1(17.32,15.11)
  TOP w0.305: U4.8 25.9,16.57 26.19,16.87 26.39,16.87 ; C40.1 23.45,4.98 U5.3 U5.2 U5.1 23.46,5.98 C39.1 ; U4.5 27.39,16.47 v1(27,16.87) 26.39,16.87 ; 26.39,16.87 26.4,16.86 U4.7 ; C38.1 24.94,7.54 25.45,7.04 25.55,7.04 U5.16 U5.15 ; U5.10 v1(28.64,4.98)
  TOP w0.381: v1(27,16.87) C1.1
  TOP w0.635: 26.08,20.17 D1.5 ; 26.08,20.17 26.62,20.71 26.62,21.89 27.69,22.96 C45.1 27.96,23.73 v1(29.07,23.73) ; 26.08,20.17 26.59,19.65 26.59,18.8 27,18.39 C1.1 ; v1(13.64,10.49) U2.2
  TOP w0.889: C39.1 23.21,7.58 v1(23.95,8.33) C38.1 ; P4.9 v1(5.6,15.16)
  L3_SIG w0.635: v1(29.06,20.55) 29.97,21.46 29.97,23.09 29.34,23.73 v1(29.07,23.73)
  BOTTOM w0.889: v1(23.95,8.33) 15.8,8.33 ; v1(23.95,8.33) 23.95,7.67 26.64,4.98 v1(28.64,4.98) ; v1(23.95,8.33) 23.95,10.01 27.64,13.69 27.64,15.32 27,15.95 ; 15.8,8.33 v1(13.64,10.49) 13.64,11.23 15.81,13.4 16.45,13.4 17.34,14.29 17.34,14.97 17.32,14.99 v1(17.32,15.11) ; 15.8,8.33 15.04,7.57 10.16,7.57 9.09,8.64 9.09,11.67 v1(5.6,15.16) ; 27,15.95 v1(27,16.87) ; 27,15.95 C46.1
SPI_CSB: length 26.7
  TOP w0.127: v2(17.02,28.19) 16.61,28.6 16.61,31.57 15.95,32.23 13.46,32.23 12.72,32.97 R2.2
  TOP w0.254: v2(17.02,28.19) 17.83,28.19 U1.C1
  BOTTOM w0.127: R19.1 3.8,27.7 4.29,28.19 v2(17.02,28.19)
SPI_MISO: length 13.8
  TOP w0.254: U1.C2 v2(19.16,26.37)
  BOTTOM w0.127: R20.2 7.43,25.16 10,27.73 18.07,27.73 19.16,26.63 v2(19.16,26.37)
SPI_MOSI: length 23
  TOP w0.254: U1.D5 v2(18.14,23.44)
  BOTTOM w0.127: R22.2 7.41,26.71 7.09,26.39 5.21,26.39 4.5,25.68 4.5,22.75 5.35,21.89 9.4,21.89 10.08,21.21 16.21,21.21 16.36,21.06 16.71,21.06 17.25,21.59 17.25,22.71 17.98,23.44 v2(18.14,23.44)
SPI_SCLK: length 13.3
  TOP w0.254: U1.D4 v2(18.08,24.18)
  BOTTOM w0.127: v2(18.08,24.18) 17.68,23.77 15.9,23.77 13.69,21.56 11.38,21.56 9.25,23.7 7.95,23.7 7.43,23.18 R21.2
SS_DM: length 5.2
  TOP w0.127: D1.6 25.33,19.22 24.62,19.93 21.04,19.93 U1.A10
SS_DP: length 5.3
  TOP w0.127: D1.4 25.33,21.12 24.4,20.19 21.04,20.19 U1.A9
SSDM: length 10.3
  TOP w0.127: M1.B7 31.25,21.98 v2(30.81,21.54) ; D1.1 27.68,19.48 27.46,19.48 27.23,19.71 27.23,21.64 28.49,22.9 v1(29.15,22.9) 29.32,22.73 M1.A7
  BOTTOM w0.127: v1(29.15,22.9) 29.55,22.5 30.93,22.5 31.17,22.27 31.17,21.89 v2(30.81,21.54)
SSDP: length 5.6
  TOP w0.127: D1.3 27.95,21.99 28.18,22.23 v1(29.15,22.23) 29.15,22.23 M1.A6 ; v2(30.76,22.1) 31.14,22.48 M1.B6
  BOTTOM w0.127: v2(30.76,22.1) 30.63,22.23 v1(29.15,22.23)
U3RX_VDDQ: length 9.2
  TOP w0.254: U1.A2 21.78,27.08 21.8,27.08 v1(21.8,27.08)
  BOTTOM w0.254: v1(21.8,27.08) 24.8,27.08 E4.1
  BOTTOM w0.508: C16.1 C17.1
  BOTTOM w0.635: E4.1 C17.1
U3TX_VDDQ: length 7.5
  TOP w0.254: E3.1 23.91,25.68 C21.1 23.74,24.16 C20.1 22.48,22.99 21.42,24.04 20.35,24.04 U1.B5
UNNAMED_4_ADM7172_I197_SS: length 1.3
  TOP w0.305: C47.1 U4.4
UNNAMED_4_CAP_I116_N1: length 15.6
  TOP w0.127: C2.1 15.72,33.03 16.94,31.8 16.94,29.26 17.58,28.63 17.96,28.63 19.58,27 19.58,24.08 U1.C5
  TOP w0.381: C2.1 R10.2 15.57,34.87 15.57,35.26 14.67,36.16 S1.2
UNNAMED_4_CAP_I140_N1: length 6.8
  TOP w0.254: U1.B6 v2(20.19,22.63)
  BOTTOM w0.254: v2(20.19,22.63) 21.12,23.56 E1.2
  BOTTOM w0.381: C22.1 C23.1 E1.2
UNNAMED_4_CN16PODDEVEN_I209_N2: length 6.4
  TOP w0.305: P3.3 6.28,25.16 5.31,26.14 v1(2.24,26.14)
  BOTTOM w0.178: v1(2.24,26.14) 2.24,25.73 R19.2
UNNAMED_4_CN16PODDEVEN_I210_N1: length 2.9
  TOP w0.305: P3.2 v1(4.94,23.16)
  BOTTOM w0.178: v1(4.94,23.16) 4.96,23.18 R21.1
UNNAMED_4_CN16PODDEVEN_I210_N2: length 2.9
  TOP w0.889: v1(4.94,25.16) 4.94,25.16 P3.4
  BOTTOM w0.178: v1(4.94,25.16) 6.41,25.16 R20.1
UNNAMED_4_CN16PODDEVEN_I210_N3: length 2.9
  TOP w0.889: P3.6 4.77,27.16 v1(4.77,27.17)
  BOTTOM w0.178: v1(4.77,27.17) R22.1
UNNAMED_4_DIOLED_I220_N: length 1.4
  TOP w0.127: DS3.C 9.82,18.15 R3.1
UNNAMED_4_DIOLED_I221_N: length 1.4
  TOP w0.127: DS2.C 11.69,34.02 R2.1
UNNAMED_4_DIOLED_I222_P: length 1.4
  TOP w0.635: DS1.A R1.2
UNNAMED_4_ICCYUSB301X_I101_FSLC: length 6.5
  TOP w0.254: U1.B2 20.19,26.29 v2(20.19,26.34) ; v2(17.78,22.64) U1.E6 ; v2(20.19,24.69) U1.B4
  L3_SIG w0.127: v2(20.19,24.69) v2(20.19,26.34)
  BOTTOM w0.127: v2(17.78,22.64) 18.15,22.64 v2(20.19,24.69) 20.56,24.69 R11.2
UNNAMED_4_ICCYUSB301X_I101_RU_1: length 6
  TOP w0.127: R12.1 23.35,29.03 22.25,27.94 22.25,26.9 21,25.65 20.36,25.65 U1.B3
UNNAMED_4_ICCYUSB301X_I101_RUSB: length 0.9
  TOP w0.254: U1.C8 v2(19.48,21.26)
  BOTTOM w0.381: R13.1 19.48,20.72 v2(19.48,21.26)
UNNAMED_4_MODUSB24P6PSHLD_I16_1: length 1.2
  TOP w0.127: M1.B5 v2(30.99,22.98)
  BOTTOM w0.127: v2(30.99,22.98) 30.99,23.44 R17.1
UNNAMED_4_MODUSB24P6PSHLD_I16_2: length 8.9
  TOP w0.889: M1.SH5 31.86,18.62 32.54,18.62 M1.SH6 ; 32.62,25.95 31.89,26.67 M1.SH4
  BOTTOM w0.381: 32.62,25.95 33.57,25.95 34.29,26.67 35.73,26.67
  BOTTOM w0.635: M1.SH4 31.28,25.17 R18.1
UNNAMED_4_MODUSB24P6PSHLD_I165_: length 2.4
  TOP w0.127: M1.A5 29.93,21.77 29.23,21.77 v1(29,21.54)
  BOTTOM w0.127: v1(29,21.54) 29.95,20.6 R16.1
XTALIN: length 13.6
  TOP w0.127: Y1.3 21.26,30.66 v1(20.36,30.66) 19.87,30.66 C4.1
  TOP w0.254: v2(19.39,23.08) U1.C6
  L3_SIG w0.127: v2(19.39,23.08) 19.84,23.53 19.84,23.76 22.28,26.19 22.28,28.96 23.06,29.75 23.06,30.23 22.63,30.66 v1(20.36,30.66)
XTALOUT: length 13.5
  TOP w0.127: Y1.1 23.04,31.88 v1(24.02,31.88) 24.44,31.88 C3.1
  TOP w0.254: U1.C7 v2(19.53,22.43)
  L3_SIG w0.127: v1(24.02,31.88) 24.02,30.34 22.53,28.85 22.53,26.09 20.09,23.65 20.09,23.32 19.79,23.01 19.79,22.68 v2(19.53,22.43)

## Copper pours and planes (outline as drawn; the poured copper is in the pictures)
DGND on TOP: 29.44,16.26 29.44,12.7 27.91,12.7 27.91,13.67 25.37,13.67 25.37,12.7 23.85,12.7 23.85,16.26 25.37,16.26 25.37,15.29 27.91,15.29 27.91,16.26
DGND on L2_GND, L5_GND: 0.64,44.07 0.64,0.64 37.47,0.64 37.47,44.07
DUT_3P3V on TOP: 27.05,13.36 27.05,12.7 26.42,12.07 26.42,10.9 26.87,10.44 27.38,10.44 27.56,10.26 27.56,9.93 27.41,9.78 24.99,9.78 24.99,10.44 25.45,10.9 25.45,11.96 25.76,12.27 25.73,13.36 25.83,13.46 26.95,13.46
FX3_1P2V on TOP: 26.9,4.09 27,4.19 28.85,4.19 28.91,4.24 29.87,4.24 29.87,3.23 28.91,3.23 28.85,3.28 27,3.28 26.9,3.38
FX3_1P2V on L3_SIG: 0.64,44.07 0.64,0.64 37.47,0.64 37.47,44.07
FX3_1P8V on TOP: 25.88,4.09 25.96,4.17 26.14,4.17 26.21,4.09 26.21,2.95 26.54,2.62 26.54,1.63 25.58,1.63 25.58,2.64 25.88,2.95
FX3_3P3V on TOP: 22.73,3.73 25.27,3.73 25.4,3.86 25.4,4.09 25.48,4.17 25.63,4.17 25.7,4.09 25.7,3.38 25.07,2.74 22.73,2.74
FX3_3P3V on L4_PWR: 0.64,44.07 0.64,0.64 37.47,0.64 37.47,44.07
FX3_VBUS on TOP: 26.57,16.51 26.67,16.61 27.03,16.61 27.23,16.41 27.23,15.6 27.33,15.49 27.46,15.49 27.53,15.57 27.56,16.54 27.3,16.79 27.3,17.75 26.7,17.75 26.67,17.6 25.7,16.64 25.7,15.57 25.83,15.44 26.47,15.44 26.57,15.54
FX3_VBUS on TOP: 25.25,4.93 25.25,6.02 25.5,6.27 26.11,6.27 26.21,6.38 26.21,7.09 26.11,7.19 25.63,7.19 25.43,7.39 25.43,8.81 25.4,8.84 23.83,8.84 22.73,7.75 22.73,4.24 23.67,4.24 23.67,4.75 23.75,4.83 25.15,4.83
UNNAMED_4_MODUSB24P6PSHLD_I16_2 on BOTTOM: 29.44,27.51 29.18,27.25 29.18,26.11 29.44,25.86 30.2,25.86 30.45,25.6 30.45,24.33 30.61,24.18 31.45,24.18 31.6,24.33 31.6,24.97 31.85,25.22 34.92,25.22 35.15,24.99 35.15,19.76 34.9,19.51 30.84,19.51 30.58,19.25 30.58,19 30.33,18.75 29.44,18.75 29.18,18.49 29.18,17.35 29.44,17.09 37.06,17.09 37.31,17.35 37.31,27.25 37.06,27.51

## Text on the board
BOTTOM: LY6-BOTTOM METAL
Board Geometry/Soldermask Bottom: BOTTOK SOLDERMASK
Package Geometry/Pastemask Bottom: BOTTOM SOLDERPASTE
Ref Des/Silkscreen Bottom: R4 = PMODE2 HI | R5 = PMODE1 HI | R6 = PMODE0 HI | R7 = PMODE2 LOW | R8 = PMODE1 LOW | R9 = PMODE0 LOW | DEFAULT JUMPER SETTING | PMODE1 HI | PMODE0 FLOAT | PMODE2 FLOAT | POWER | RETURN/GND | BOTTOM SILKSCREEN
User.Comments: A | INITIAL RELEASE: NHR-059241 | 12/6/19 | J.CHONG | 1 | ASSEMBLY NOTES: | A1 | TOP ASSEMBLY DRAWING | BOTTOM ASSEMBLY DRAWING
TOP: LY1-TOP METAL
Board Geometry/Soldermask Top: TOP SOLDERMASK
Package Geometry/Pastemask Top: TOP SOLDERPASTE
Ref Des/Silkscreen Top: RETURN/GND | POWER | JC/BEL | 12/06/19 | 08-059334-01-a1 | TOP SILKSCREEN
L2_GND: LY2-GND
L3_SIG: LY3-SIG/PWR
L4_PWR: LY4-SIG/PWR
L5_GND: LY5-GND
XSECTION_CHART: *  SURFACE - AIR 0 MIL(+0/-0) | L1 TOP CONDUCTOR - COPPER 1.2 MIL(+0/-0) | *  DIELECTRIC - FR-4 10 MIL(+0/-0) | L2 L2_GND CONDUCTOR - COPPER 1.2 MIL(+0/-0) | L3 L3_SIG CONDUCTOR - COPPER 1.2 MIL(+0/-0) | *  DIELECTRIC - FR-4 15 MIL(+0/-0) | L4 L4_PWR CONDUCTOR - COPPER 1.2 MIL(+0/-0) | L5 L5_GND CONDUCTOR - COPPER 1.2 MIL(+0/-0) | L6 BOTTOM CONDUCTOR - COPPER 1.2 MIL(+0/-0) | DESIGN CROSS SECTION CHART | ___________________________ | TOTAL THICKNESS 62.2 MIL | 1-6
PAGE_OUTLINE: 08-059334-01-a1 | Customer Evaluation Brd
DIMENSION: DRILL DRAWING
User.13: FIGURE | SIZE | 0.098 | 8.0 | 10.0 | 24.0 | 45.0 | 96.0 | 33x20 | 51x25 | 79x25 | PLATED | NON-PLATED | FINISHED HOLES IN MILS | ALL UNITS ARE IN MILS | QTY | 1 | 46 | 103 | 4 | 2 | TOLERANCE/NOTES
User.16: Combo of 2 slots to make 1 L shape cutout | 51.0x25.0 & 79.0x25.0 Non-Plated | 79.0x25.0 Non-Plated Slot | 33.0x20.0 Non-Plated Slot | 2 Of these Slots Used to | help Form L shape Cutouts | These Slots used to help | form the L shape Cutouts | SLOT | IGNORE THIS DRILL
